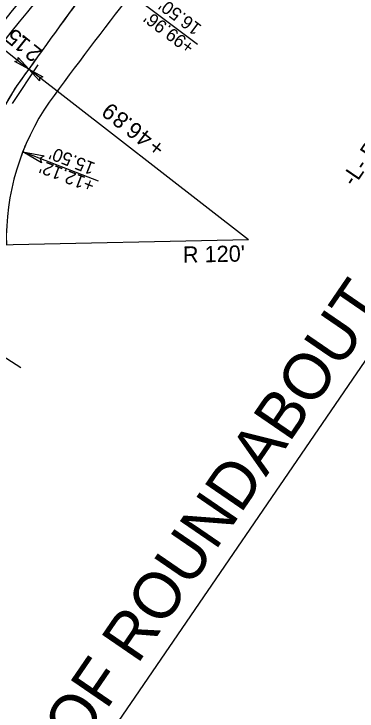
# Model space of a CAD drawing. Extents: x 1975573 to 1977432, y 778300 to 780514.
# Drawn here: x 1976462.7 to 1976647.7, y 779204.8 to 779580.6 of the extents above; entities that cross this region are included whole.
import ezdxf

# ---------------------------------------------------------------- set-up
doc = ezdxf.new("R2010")
doc.units = 0
for name, color, linetype in [('Prop Conc 2ft 6in Curb and Gutter', 7, 'Continuous'), ('Prop Conc 4in Sidewalk', 7, 'Continuous'), ('Prop Conc Drive Radius Type', 7, 'Continuous'), ('Prop Dimension', 7, 'Continuous'), ('Prop Dimension Text', 7, 'Continuous'), ('Prop EOT', 7, 'Continuous'), ('Prop Horizontal Alignment', 7, 'Continuous'), ('Prop Horizontal Alignment Station Label', 7, 'Continuous'), ('Prop Lane Lines', 7, 'Continuous'), ('Prop Terminator CELL', 7, 'Continuous'), ('Typical Terminator CELL', 7, 'Continuous')]:
    doc.layers.add(name, color=color, linetype=linetype)

# ---------------------------------------------------------------- blocks, each defined once
blk = doc.blocks.new('TERMINATOR')
at = {"layer": 'Typical Terminator CELL'}
blk.add_lwpolyline([(-0.469, 0.081), (0, 0), (-0.471, -0.083), (-0.411, 0)], close=True, dxfattribs=at)

msp = doc.modelspace()

# ---------------------------------------------------------------- linework, layer by layer
at = {"layer": 'Prop Conc 2ft 6in Curb and Gutter'}
for centre, radius, start, end in [((1978239.96, 778006.13), 2403.74, 136.72119, 139.7323), ((1981863.71, 775482.94), 6259.88, 141.013904, 146.823865)]:
    msp.add_arc(centre, radius, start, end, dxfattribs=at)
at = {"layer": 'Prop Conc 4in Sidewalk'}
msp.add_lwpolyline([(1976470.68, 779550.79), (1976470.68, 779550.79)], dxfattribs=at)
for centre, radius, start, end in [((1978392.04, 778191.34), 2353.66, 143.11825, 144.71902), ((1978392.04, 778191.34), 2353.66, 143.11825, 144.7184), ((1978364.97, 778155.71), 2333.19, 142.02902, 143.82111), ((1978364.97, 778155.71), 2333.19, 142.02902, 143.82111), ((1976589.17, 779458.81), 150, 142.1787, 158.8164), ((1976589.17, 779458.81), 150, 142.1787, 158.8164), ((1978385.78, 778195.91), 2345.91, 144.72104, 144.72166), ((1976589.17, 779458.81), 130.63, 145.3825, 181.1936), ((1976589.17, 779458.81), 130.62, 145.3825, 181.1936)]:
    msp.add_arc(centre, radius, start, end, dxfattribs=at)
at = {"layer": 'Prop Conc Drive Radius Type'}
msp.add_line((1976475.61, 779553.23), (1976461.7, 779532.36), dxfattribs=at)
at = {"layer": 'Prop Dimension'}
for p, q in [((1976561.64, 779564.2), (1976525.64, 779591.2)), ((1976423.7, 779059.98), (1976774.88, 779572.85)), ((1976468.61, 779509.21), (1976468.75, 779509.57)), ((1976508.32, 779490.51), (1976467.49, 779506.31)), ((1976434.79, 779410.19), (1976466.33, 779389.91))]:
    msp.add_line(p, q, dxfattribs=at)
at = {"layer": 'Prop Dimension Text'}
for p, q in [((1976449.69, 779567.6), (1976470.68, 779550.79)), ((1976589.17, 779458.81), (1976470.68, 779550.79)), ((1976589.17, 779458.81), (1976439.2, 779455.68))]:
    msp.add_line(p, q, dxfattribs=at)
at = {"layer": 'Prop EOT'}
for centre, radius, start, end in [((1978239.96, 778006.13), 2401.24, 136.7176, 139.73317), ((1978385.78, 778195.91), 2345.91, 143.11561, 144.72166), ((1976589.17, 779458.81), 150, 142.1787, 181.1936), ((1981864.44, 775482.42), 6263.77, 141.014379, 146.822819)]:
    msp.add_arc(centre, radius, start, end, dxfattribs=at)
at = {"layer": 'Prop Horizontal Alignment'}
for centre, radius, start, end in [((1978303.2, 778082.63), 2375, 135.73946, 152.1381), ((1981863.71, 775482.94), 6300, 141.013904, 146.814735)]:
    msp.add_arc(centre, radius, start, end, dxfattribs=at)
at = {"layer": 'Prop Lane Lines'}
for radius, end in [(2381.88, 141.94983), (2368.12, 141.23948)]:
    msp.add_arc((1978303.2, 778082.63), radius, 135.73946, end, dxfattribs=at)
at = {"layer": 'Prop Terminator CELL'}
for points in [[(1976465, 779557.2), (1976470.68, 779550.79), (1976463.12, 779554.92), (1976464.9, 779555.42)], [(1976476.45, 779544.46), (1976470.68, 779550.79), (1976478.3, 779546.77), (1976476.53, 779546.24)]]:
    msp.add_lwpolyline(points, close=True, dxfattribs=at)

# ---------------------------------------------------------------- block references
at = {"layer": 'Prop Dimension', "xscale": 24.499999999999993, "yscale": 24.499999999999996, "rotation": 158.84470189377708}
msp.add_blockref('TERMINATOR', (1976467.49, 779506.31), dxfattribs=at)

# ---------------------------------------------------------------- texts
at = {"layer": 'Prop Dimension'}
for s, rotation, p in [("16.50'", 143.1263, (1976564.37, 779574.09)), ("+99.96'", 143.1263, (1976560.69, 779564.08)), ("15.50'", 158.8447, (1976507.01, 779500.06)), ("+12.12'", 158.8447, (1976506.8, 779490.64))]:
    msp.add_text(s, height=7, rotation=rotation, dxfattribs=at).set_placement(p)
at = {"layer": 'Prop Dimension Text'}
for s, height, rotation, p in [('5', 8.75, 141.2995, (1976467.84, 779569.27)), ('1', 8.75, 141.2995, (1976472.35, 779565.65)), ('.', 8.75, 141.2995, (1976469.67, 779567.81)), ('2', 8.75, 141.2995, (1976478.48, 779560.74)), ('9', 8.75, 142.1787, (1976519.7, 779529.35)), ('DETAIL OF ROUNDABOUT @ -Y2-', 25, 55.5983, (1976426.44, 779079.33)), ('8', 8.75, 142.1787, (1976525.47, 779524.87)), ('6', 8.75, 142.1787, (1976532.87, 779519.13)), ('.', 8.75, 142.1787, (1976527.32, 779523.44)), ('4', 8.75, 142.1787, (1976538.42, 779514.82)), ('+', 8.75, 142.1787, (1976544.95, 779509.75)), ("R 120'", 8.75, 1.1936, (1976553.88, 779446.45))]:
    msp.add_text(s, height=height, rotation=rotation, dxfattribs=at).set_placement(p)
at = {"layer": 'Prop Horizontal Alignment Station Label'}
msp.add_text('-L- PTSta.  25+31.27', height=8.75, rotation=55.7257, dxfattribs=at).set_placement((1976646.04, 779487.1))

doc.saveas('drawing.dxf')
